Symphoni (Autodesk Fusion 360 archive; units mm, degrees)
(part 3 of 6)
sketch "Sketch8" plane through (0, 0, 18.7) normal (0, 0, 1) x axis (-1, 0, 0)
  line L1 (-53.7625, -51.3779) -> (-53.7625, -105.1735)
  line L2 (53.8484, -51.3779) -> (-53.7625, -51.3779)
  line L3 (53.8484, -76.4735) -> (53.8484, -51.3779)
  line L4 (53.8485, -76.4735) -> (53.8484, -76.4735)
  line L5 (53.8485, -78.1735) -> (53.8485, -76.4735)
  line L6 (53.8484, -78.1735) -> (53.8485, -78.1735)
  line L7 (53.8484, -103.4735) -> (53.8484, -78.1735)
  line L8 (53.8485, -103.4735) -> (53.8484, -103.4735)
  line L9 (53.8485, -105.1735) -> (53.8485, -103.4735)
  line L10 (-53.7625, -105.1735) -> (53.8485, -105.1735)
  line L11 (-53.7625, -15.5942) -> (-53.7625, -42.5942)
  line L12 (53.8484, -15.5942) -> (-53.7625, -15.5942)
  line L13 (53.8484, -42.5942) -> (53.8484, -15.5942)
  line L14 (-53.7625, -42.5942) -> (53.8484, -42.5942)
  line L15 (50.919, -115) -> (-51.081, -115)
  line L16 (60.919, 105) -> (60.919, -105)
  line L17 (-51.081, 115) -> (50.919, 115)
  line L18 (-61.081, -105) -> (-61.081, 105)
  line L19 (39.2266, 75.4964) -> (39.2266, 70.1236)
  line L20 (32.1734, 75.4964) -> (39.2266, 75.4964)
  line L21 (32.1734, 70.1236) -> (32.1734, 75.4964)
  line L22 (39.2266, 70.1236) -> (32.1734, 70.1236)
  line L23 (8.1634, 70.1236) -> (8.1634, 75.4964)
  line L24 (15.2166, 70.1236) -> (8.1634, 70.1236)
  line L25 (15.2166, 75.4964) -> (15.2166, 70.1236)
  line L26 (8.1634, 75.4964) -> (15.2166, 75.4964)
  line L27 (-39.8766, 70.1236) -> (-39.8766, 75.4964)
  line L28 (-32.8234, 70.1236) -> (-39.8766, 70.1236)
  line L29 (-32.8234, 75.4964) -> (-32.8234, 70.1236)
  line L30 (-39.8766, 75.4964) -> (-32.8234, 75.4964)
  line L31 (-8.33, 76.81) -> (-16.33, 76.81)
  line L32 (-16.33, 76.81) -> (-16.33, 68.81)
  line L33 (-8.33, 68.81) -> (-8.33, 76.81)
  line L34 (-16.33, 68.81) -> (-8.33, 68.81)
  line L35 (49.265, 58.435) -> (-47.355, 58.435)
  line L36 (-47.355, 58.435) -> (-47.355, 95.355)
  line L37 (49.265, 95.355) -> (49.265, 58.435)
  line L38 (-47.355, 95.355) -> (49.265, 95.355)
  line L39 (42.697, 79.0319) -> (42.697, 66.5547)
  line L40 (28.703, 66.5547) -> (28.703, 79.0319)
  line L41 (41.9553, 65.813) -> (29.4447, 65.813)
  line L42 (29.372, 79.807) -> (42.028, 79.807)
  line L43 (4.693, 66.5881) -> (4.693, 79.0653)
  line L44 (18.687, 79.0653) -> (18.687, 66.5881)
  line L45 (5.4347, 79.807) -> (17.9453, 79.807)
  line L46 (18.018, 65.813) -> (5.362, 65.813)
  line L47 (-43.347, 66.5881) -> (-43.347, 79.0653)
  line L48 (-29.353, 79.0653) -> (-29.353, 66.5881)
  line L49 (-42.6053, 79.807) -> (-30.0947, 79.807)
  line L50 (-30.022, 65.813) -> (-42.678, 65.813)
  line L51 (25.203, 66.5547) -> (25.203, 79.0319)
  curve K1 (29.4447, 62.313) -> (25.203, 66.5547)
  line L52 (41.9553, 62.313) -> (29.4447, 62.313)
  curve K2 (46.197, 66.5547) -> (41.9553, 62.313)
  line L53 (46.197, 79.0319) -> (46.197, 66.5547)
  curve K3 (42.028, 83.307) -> (46.197, 79.0319)
  line L54 (29.372, 83.307) -> (42.028, 83.307)
  curve K4 (25.203, 79.0319) -> (29.372, 83.307)
  line L55 (22.187, 79.0653) -> (22.187, 66.5881)
  curve K5 (17.9453, 83.307) -> (22.187, 79.0653)
  line L56 (5.4347, 83.307) -> (17.9453, 83.307)
  curve K6 (1.193, 79.0653) -> (5.4347, 83.307)
  line L57 (1.193, 66.5881) -> (1.193, 79.0653)
  curve K7 (5.362, 62.313) -> (1.193, 66.5881)
  line L58 (18.018, 62.313) -> (5.362, 62.313)
  curve K8 (22.187, 66.5881) -> (18.018, 62.313)
  line L59 (-25.853, 79.0653) -> (-25.853, 66.5881)
  curve K9 (-30.0947, 83.307) -> (-25.853, 79.0653)
  line L60 (-42.6053, 83.307) -> (-30.0947, 83.307)
  curve K10 (-46.847, 79.0653) -> (-42.6053, 83.307)
  line L61 (-46.847, 66.5881) -> (-46.847, 79.0653)
  curve K11 (-42.678, 62.313) -> (-46.847, 66.5881)
  line L62 (-30.022, 62.313) -> (-42.678, 62.313)
  curve K12 (-25.853, 66.5881) -> (-30.022, 62.313)
  curve K13 (5.362, 62.313) -> (1.193, 66.5881)
  line L63 (18.018, 62.313) -> (5.362, 62.313)
  curve K14 (22.187, 66.5881) -> (18.018, 62.313)
  line L64 (22.187, 79.0653) -> (22.187, 66.5881)
  curve K15 (17.9453, 83.307) -> (22.187, 79.0653)
  line L65 (5.4347, 83.307) -> (17.9453, 83.307)
  curve K16 (1.193, 79.0653) -> (5.4347, 83.307)
  line L66 (1.193, 66.5881) -> (1.193, 79.0653)
  line L67 (-5.982, 62.313) -> (-18.638, 62.313)
  curve K17 (-1.813, 66.5881) -> (-5.982, 62.313)
  line L68 (-1.813, 79.0653) -> (-1.813, 66.5881)
  curve K18 (-6.0547, 83.307) -> (-1.813, 79.0653)
  line L69 (-18.5653, 83.307) -> (-6.0547, 83.307)
  curve K19 (-22.807, 79.0653) -> (-18.5653, 83.307)
  line L70 (-22.807, 66.5881) -> (-22.807, 79.0653)
  curve K20 (-18.638, 62.313) -> (-22.807, 66.5881)
  line L71 (-35.3, 21.6) -> (-35.3, 21.8)
  line L72 (-35.3, 21.6) -> (-37.3, 21.6)
  line L73 (-37.3, 21.6) -> (-37.3, 21.8)
  line L74 (-37.3, 21.8) -> (-41.05, 21.8)
  line L75 (-31.55, 21.8) -> (-35.3, 21.8)
  line L76 (-41.05, 21.8) -> (-41.05, 22.8)
  line L77 (-31.55, 22.8) -> (-31.55, 21.8)
  line L78 (-41.05, 32.8) -> (-41.05, 22.8)
  line L79 (-31.55, 32.8) -> (-41.05, 32.8)
  line L80 (-31.55, 22.8) -> (-31.55, 32.8)
  line L81 (-11.3, 21.6) -> (-11.3, 21.8)
  line L82 (-11.3, 21.6) -> (-13.3, 21.6)
  line L83 (-13.3, 21.6) -> (-13.3, 21.8)
  line L84 (-13.3, 21.8) -> (-17.05, 21.8)
  line L85 (-7.55, 21.8) -> (-11.3, 21.8)
  line L86 (-17.05, 21.8) -> (-17.05, 22.8)
  line L87 (-7.55, 22.8) -> (-7.55, 21.8)
  line L88 (-17.05, 32.8) -> (-17.05, 22.8)
  line L89 (-7.55, 32.8) -> (-17.05, 32.8)
  line L90 (-7.55, 22.8) -> (-7.55, 32.8)
  line L91 (12.7, 21.6) -> (12.7, 21.8)
  line L92 (12.7, 21.6) -> (10.7, 21.6)
  line L93 (10.7, 21.6) -> (10.7, 21.8)
  line L94 (10.7, 21.8) -> (6.95, 21.8)
  line L95 (16.45, 21.8) -> (12.7, 21.8)
  line L96 (6.95, 21.8) -> (6.95, 22.8)
  line L97 (16.45, 22.8) -> (16.45, 21.8)
  line L98 (6.95, 32.8) -> (6.95, 22.8)
  line L99 (16.45, 32.8) -> (6.95, 32.8)
  line L100 (16.45, 22.8) -> (16.45, 32.8)
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  dimension "d24" = 3.5
  dimension "d25" = 3.5
  dimension "d26" = 3.5
extrude "Extrude7" add sketch "Sketch8" along normal blind 2.349
delete_face "DeleteFace6"
component_insert "Component Insert5"
sketch "Sketch9" plane through (0, 0, 10.185) normal (0, 0, 1) x axis (-1, 0, 0)
  line L1 (-7.83, 77.31) -> (-16.83, 77.31)
  line L2 (-7.83, 68.31) -> (-7.83, 77.31)
  line L3 (-16.83, 68.31) -> (-7.83, 68.31)
  line L4 (-16.83, 77.31) -> (-16.83, 68.31)
  line L5 (27.453, 77.907) -> (28.6, 77.907)
  line L6 (27.453, 78.857) -> (27.453, 77.907)
  line L7 (33.753, 81.057) -> (29.653, 81.057)
  line L8 (33.753, 78.91) -> (33.753, 81.057)
  line L9 (37.647, 78.91) -> (33.753, 78.91)
  line L10 (37.647, 81.057) -> (37.647, 78.91)
  line L11 (41.747, 81.057) -> (37.647, 81.057)
  line L12 (43.947, 77.907) -> (43.947, 78.857)
  line L13 (42.8, 77.907) -> (43.947, 77.907)
  line L14 (42.8, 74.757) -> (42.8, 77.907)
  line L15 (41.8, 74.757) -> (42.8, 74.757)
  line L16 (41.8, 70.863) -> (41.8, 74.757)
  line L17 (42.8, 70.863) -> (41.8, 70.863)
  line L18 (42.8, 67.713) -> (42.8, 70.863)
  line L19 (43.947, 67.713) -> (42.8, 67.713)
  line L20 (43.947, 66.763) -> (43.947, 67.713)
  line L21 (37.647, 64.563) -> (41.747, 64.563)
  line L22 (37.647, 66.71) -> (37.647, 64.563)
  line L23 (33.753, 66.71) -> (37.647, 66.71)
  line L24 (33.753, 64.563) -> (33.753, 66.71)
  line L25 (29.653, 64.563) -> (33.753, 64.563)
  line L26 (27.453, 67.713) -> (27.453, 66.763)
  line L27 (28.6, 67.713) -> (27.453, 67.713)
  line L28 (28.6, 70.863) -> (28.6, 67.713)
  line L29 (29.6, 70.863) -> (28.6, 70.863)
  line L30 (29.6, 74.757) -> (29.6, 70.863)
  line L31 (28.6, 74.757) -> (29.6, 74.757)
  line L32 (28.6, 77.907) -> (28.6, 74.757)
  line L33 (-30.25, 74.757) -> (-29.25, 74.757)
  line L34 (-30.25, 70.863) -> (-30.25, 74.757)
  line L35 (-29.25, 70.863) -> (-30.25, 70.863)
  line L36 (-29.25, 67.713) -> (-29.25, 70.863)
  line L37 (-28.103, 67.713) -> (-29.25, 67.713)
  line L38 (-28.103, 66.763) -> (-28.103, 67.713)
  line L39 (-34.403, 64.563) -> (-30.303, 64.563)
  line L40 (-34.403, 66.71) -> (-34.403, 64.563)
  line L41 (-38.297, 66.71) -> (-34.403, 66.71)
  line L42 (-38.297, 64.563) -> (-38.297, 66.71)
  line L43 (-42.397, 64.563) -> (-38.297, 64.563)
  line L44 (-44.597, 67.713) -> (-44.597, 66.763)
  line L45 (-43.45, 67.713) -> (-44.597, 67.713)
  line L46 (-43.45, 70.863) -> (-43.45, 67.713)
  line L47 (-42.45, 70.863) -> (-43.45, 70.863)
  line L48 (-42.45, 74.757) -> (-42.45, 70.863)
  line L49 (-43.45, 74.757) -> (-42.45, 74.757)
  line L50 (-43.45, 77.907) -> (-43.45, 74.757)
  line L51 (-44.597, 77.907) -> (-43.45, 77.907)
  line L52 (-44.597, 78.857) -> (-44.597, 77.907)
  line L53 (-38.297, 81.057) -> (-42.397, 81.057)
  line L54 (-38.297, 78.91) -> (-38.297, 81.057)
  line L55 (-34.403, 78.91) -> (-38.297, 78.91)
  line L56 (-34.403, 81.057) -> (-34.403, 78.91)
  line L57 (-30.303, 81.057) -> (-34.403, 81.057)
  line L58 (-28.103, 77.907) -> (-28.103, 78.857)
  line L59 (-29.25, 77.907) -> (-28.103, 77.907)
  line L60 (-29.25, 74.757) -> (-29.25, 77.907)
  line L61 (5.59, 70.863) -> (4.59, 70.863)
  line L62 (5.59, 74.757) -> (5.59, 70.863)
  line L63 (4.59, 74.757) -> (5.59, 74.757)
  line L64 (4.59, 77.907) -> (4.59, 74.757)
  line L65 (3.443, 77.907) -> (4.59, 77.907)
  line L66 (3.443, 78.857) -> (3.443, 77.907)
  line L67 (9.743, 81.057) -> (5.643, 81.057)
  line L68 (9.743, 78.91) -> (9.743, 81.057)
  line L69 (13.637, 78.91) -> (9.743, 78.91)
  line L70 (13.637, 81.057) -> (13.637, 78.91)
  line L71 (17.737, 81.057) -> (13.637, 81.057)
  line L72 (19.937, 77.907) -> (19.937, 78.857)
  line L73 (18.79, 77.907) -> (19.937, 77.907)
  line L74 (18.79, 74.757) -> (18.79, 77.907)
  line L75 (17.79, 74.757) -> (18.79, 74.757)
  line L76 (17.79, 70.863) -> (17.79, 74.757)
  line L77 (18.79, 70.863) -> (17.79, 70.863)
  line L78 (18.79, 67.713) -> (18.79, 70.863)
  line L79 (19.937, 67.713) -> (18.79, 67.713)
  line L80 (19.937, 66.763) -> (19.937, 67.713)
  line L81 (13.637, 64.563) -> (17.737, 64.563)
  line L82 (13.637, 66.71) -> (13.637, 64.563)
  line L83 (9.743, 66.71) -> (13.637, 66.71)
  line L84 (9.743, 64.563) -> (9.743, 66.71)
  line L85 (5.643, 64.563) -> (9.743, 64.563)
  line L86 (3.443, 67.713) -> (3.443, 66.763)
  line L87 (4.59, 67.713) -> (3.443, 67.713)
  line L88 (4.59, 70.863) -> (4.59, 67.713)
  line L89 (-47.3233, 95.4822) -> (49.0612, 95.4822)
  line L90 (-47.3233, 58.6231) -> (-47.3233, 95.4822)
  line L91 (49.0612, 58.6231) -> (-47.3233, 58.6231)
  line L92 (49.0612, 95.4822) -> (49.0612, 58.6231)
  arc A1 centre (29.653, 78.857) radius 2.2 clockwise from (27.453, 78.857) to (29.653, 81.057)
  arc A2 centre (41.747, 78.857) radius 2.2 clockwise from (41.747, 81.057) to (43.947, 78.857)
  arc A3 centre (41.747, 66.763) radius 2.2 clockwise from (43.947, 66.763) to (41.747, 64.563)
  arc A4 centre (29.653, 66.763) radius 2.2 clockwise from (29.653, 64.563) to (27.453, 66.763)
  arc A5 centre (-30.303, 66.763) radius 2.2 clockwise from (-28.103, 66.763) to (-30.303, 64.563)
  arc A6 centre (-42.397, 66.763) radius 2.2 clockwise from (-42.397, 64.563) to (-44.597, 66.763)
  arc A7 centre (-42.397, 78.857) radius 2.2 clockwise from (-44.597, 78.857) to (-42.397, 81.057)
  arc A8 centre (-30.303, 78.857) radius 2.2 clockwise from (-30.303, 81.057) to (-28.103, 78.857)
  arc A9 centre (5.643, 78.857) radius 2.2 clockwise from (3.443, 78.857) to (5.643, 81.057)
  arc A10 centre (17.737, 78.857) radius 2.2 clockwise from (17.737, 81.057) to (19.937, 78.857)
  arc A11 centre (17.737, 66.763) radius 2.2 clockwise from (19.937, 66.763) to (17.737, 64.563)
  arc A12 centre (5.643, 66.763) radius 2.2 clockwise from (5.643, 64.563) to (3.443, 66.763)
sketch "Sketch10" plane through (0, 0, 21.049) normal (0, 0, 1) x axis (-1, 0, 0)
  curve K1 (-30.022, 62.313) -> (-25.853, 66.5881)
  line L1 (-42.678, 62.313) -> (-30.022, 62.313)
  curve K2 (-46.847, 66.5881) -> (-42.678, 62.313)
  line L2 (-46.847, 79.0653) -> (-46.847, 66.5881)
  curve K3 (-42.6053, 83.307) -> (-46.847, 79.0653)
  line L3 (-30.0947, 83.307) -> (-42.6053, 83.307)
  curve K4 (-25.853, 79.0653) -> (-30.0947, 83.307)
  line L4 (-25.853, 66.5881) -> (-25.853, 79.0653)
  curve K5 (-22.807, 66.5881) -> (-18.638, 62.313)
  line L5 (-22.807, 79.0653) -> (-22.807, 66.5881)
  curve K6 (-18.5653, 83.307) -> (-22.807, 79.0653)
  line L6 (-6.0547, 83.307) -> (-18.5653, 83.307)
  curve K7 (-1.813, 79.0653) -> (-6.0547, 83.307)
  line L7 (-1.813, 66.5881) -> (-1.813, 79.0653)
  curve K8 (-5.982, 62.313) -> (-1.813, 66.5881)
  line L8 (-18.638, 62.313) -> (-5.982, 62.313)
  line L9 (1.193, 79.0653) -> (1.193, 66.5881)
  curve K9 (1.2034, 79.3649) -> (1.193, 79.0653)
  curve K10 (5.4347, 83.307) -> (1.2034, 79.3649)
  line L10 (17.9453, 83.307) -> (5.4347, 83.307)
  curve K11 (18.2449, 83.2966) -> (17.9453, 83.307)
  curve K12 (22.187, 79.0653) -> (18.2449, 83.2966)
  line L11 (22.187, 66.5881) -> (22.187, 79.0653)
  curve K13 (22.0884, 65.6471) -> (22.187, 66.5881)
  curve K14 (18.018, 62.313) -> (22.0884, 65.6471)
  line L12 (5.362, 62.313) -> (18.018, 62.313)
  curve K15 (2.0685, 63.9442) -> (5.362, 62.313)
  curve K16 (1.3008, 65.6049) -> (2.0685, 63.9442)
  curve K17 (1.193, 66.5881) -> (1.3008, 65.6049)
  curve K18 (29.372, 83.307) -> (25.203, 79.0319)
  line L13 (42.028, 83.307) -> (29.372, 83.307)
  curve K19 (46.197, 79.0319) -> (42.028, 83.307)
  line L14 (46.197, 66.5547) -> (46.197, 79.0319)
  curve K20 (41.9553, 62.313) -> (46.197, 66.5547)
  line L15 (29.4447, 62.313) -> (41.9553, 62.313)
  curve K21 (25.203, 66.5547) -> (29.4447, 62.313)
  line L16 (25.203, 79.0319) -> (25.203, 66.5547)
  line L17 (53.9191, -28.5942) -> (-53.7629, -28.5942)
  line L18 (53.9191, -91.4735) -> (53.9191, -28.5942)
  line L19 (53.8485, -91.4735) -> (53.9191, -91.4735)
  line L20 (53.8485, -93.1735) -> (53.8485, -91.4735)
  line L21 (53.8484, -93.1735) -> (53.8485, -93.1735)
  line L22 (53.8484, -91.4735) -> (53.8484, -93.1735)
  line L23 (-53.7629, -91.4735) -> (53.8484, -91.4735)
  line L24 (-53.7629, -28.5942) -> (-53.7629, -91.4735)
  line L25 (-61.081, -105) -> (-61.081, 105)
  line L26 (50.919, -115) -> (-51.081, -115)
  line L27 (60.919, 105) -> (60.919, -105)
  line L28 (-51.081, 115) -> (50.919, 115)
  line L29 (-53.7629, -28.5942) -> (-53.7629, -91.4735)
  line L30 (-53.7629, -91.4735) -> (53.8484, -91.4735)
  line L31 (53.8484, -91.4735) -> (53.8484, -93.1735)
  line L32 (53.8484, -93.1735) -> (53.8485, -93.1735)
  line L33 (53.8485, -93.1735) -> (53.8485, -91.4735)
  line L34 (53.8485, -91.4735) -> (53.9191, -91.4735)
  line L35 (53.9191, -91.4735) -> (53.9191, -28.5942)
  line L36 (-48.7625, -28.5942) -> (-53.7629, -28.5942)
  line L37 (53.9191, -28.5942) -> (48.9191, -28.5942)
  line L38 (25.203, 79.0319) -> (25.203, 66.5547)
  curve K22 (25.203, 66.5547) -> (29.4447, 62.313)
  line L39 (29.4447, 62.313) -> (41.9553, 62.313)
  curve K23 (41.9553, 62.313) -> (46.197, 66.5547)
  line L40 (46.197, 66.5547) -> (46.197, 79.0319)
  curve K24 (46.197, 79.0319) -> (42.028, 83.307)
  line L41 (42.028, 83.307) -> (29.372, 83.307)
  curve K25 (29.372, 83.307) -> (25.203, 79.0319)
  curve K26 (1.193, 66.5881) -> (1.3008, 65.6049)
  curve K27 (1.3008, 65.6049) -> (2.0685, 63.9442)
  curve K28 (2.0685, 63.9442) -> (5.362, 62.313)
  line L42 (5.362, 62.313) -> (18.018, 62.313)
  curve K29 (18.018, 62.313) -> (22.0884, 65.6471)
  curve K30 (22.0884, 65.6471) -> (22.187, 66.5881)
  line L43 (22.187, 66.5881) -> (22.187, 79.0653)
  curve K31 (22.187, 79.0653) -> (18.2449, 83.2966)
  curve K32 (18.2449, 83.2966) -> (17.9453, 83.307)
  line L44 (17.9453, 83.307) -> (5.4347, 83.307)
  curve K33 (5.4347, 83.307) -> (1.2034, 79.3649)
  curve K34 (1.2034, 79.3649) -> (1.193, 79.0653)
  line L45 (1.193, 79.0653) -> (1.193, 66.5881)
  line L46 (-18.638, 62.313) -> (-5.982, 62.313)
  curve K35 (-5.982, 62.313) -> (-1.813, 66.5881)
  line L47 (-1.813, 66.5881) -> (-1.813, 79.0653)
  curve K36 (-1.813, 79.0653) -> (-6.0547, 83.307)
  line L48 (-6.0547, 83.307) -> (-18.5653, 83.307)
  curve K37 (-18.5653, 83.307) -> (-22.807, 79.0653)
  line L49 (-22.807, 79.0653) -> (-22.807, 66.5881)
  curve K38 (-22.807, 66.5881) -> (-18.638, 62.313)
  line L50 (-25.853, 66.5881) -> (-25.853, 79.0653)
  curve K39 (-25.853, 79.0653) -> (-30.0947, 83.307)
  line L51 (-30.0947, 83.307) -> (-42.6053, 83.307)
  curve K40 (-42.6053, 83.307) -> (-46.847, 79.0653)
  line L52 (-46.847, 79.0653) -> (-46.847, 66.5881)
  curve K41 (-46.847, 66.5881) -> (-42.678, 62.313)
  line L53 (-42.678, 62.313) -> (-30.022, 62.313)
  curve K42 (-30.022, 62.313) -> (-25.853, 66.5881)
  line L54 (-51.081, 115) -> (50.919, 115)
  line L55 (60.919, 105) -> (60.919, -105)
  line L56 (50.919, -115) -> (-51.081, -115)
  line L57 (-61.081, -105) -> (-61.081, 105)
  line L58 (48.9191, -71.4735) -> (48.9191, -28.5942)
  line L59 (-48.7625, -71.4735) -> (48.9191, -71.4735)
  line L60 (-48.7625, -28.5942) -> (-48.7625, -71.4735)
  curve K43 (29.372, 82.807) -> (25.703, 79.0319)
  line L61 (42.028, 82.807) -> (29.372, 82.807)
  curve K44 (45.697, 79.0319) -> (42.028, 82.807)
  line L62 (45.697, 66.5547) -> (45.697, 79.0319)
  curve K45 (41.9553, 62.813) -> (45.697, 66.5547)
  line L63 (29.4447, 62.813) -> (41.9553, 62.813)
  curve K46 (25.703, 66.5547) -> (29.4447, 62.813)
  line L64 (25.703, 79.0319) -> (25.703, 66.5547)
  circle C1 centre (11.7, 27.95) radius 3.4635
  circle C2 centre (-36.3, 27.95) radius 3.25
  circle C3 centre (-12.3, 27.95) radius 3.4635
  circle C4 centre (35.7, 27.95) radius 3.4635
  arc A1 centre (-51.081, -105) radius 10 clockwise from (-51.081, -115) to (-61.081, -105)
  arc A2 centre (50.919, -105) radius 10 clockwise from (60.919, -105) to (50.919, -115)
  arc A3 centre (50.919, 105) radius 10 clockwise from (50.919, 115) to (60.919, 105)
  arc A4 centre (-51.081, 105) radius 10 clockwise from (-61.081, 105) to (-51.081, 115)
  circle C5 centre (35.7, 27.95) radius 3.4635
  circle C6 centre (-12.3, 27.95) radius 3.4635
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  dimension "d29" = 0.5
extrude "Extrude8" new body sketch "Sketch10" profile of K45 K46 K43 L62 K44 L64 L61 L63 against normal blind 7
shell "Shell1" innerThickness 2
copy_paste_bodies "CopyPasteBodies1"
move "Move2"
move "Move3"
sketch "Sketch16" plane through (0, 0, 29.049) normal (0, 0, -1) x axis (1, 0, 0)
  curve K1 (20.297, 66.5547) -> (18.5553, 64.813)
  line L1 (20.297, 79.0319) -> (20.297, 66.5547)
  curve K2 (18.628, 80.807) -> (20.297, 79.0319)
  line L2 (5.972, 80.807) -> (18.628, 80.807)
  curve K3 (4.303, 79.0319) -> (5.972, 80.807)
  line L3 (4.303, 66.5547) -> (4.303, 79.0319)
  curve K4 (6.0447, 64.813) -> (4.303, 66.5547)
  line L4 (18.5553, 64.813) -> (6.0447, 64.813)
  line L5 (13.2555, 73.9121) -> (11.2555, 73.9121)
  line L6 (13.2555, 71.9121) -> (13.2555, 73.9121)
  line L7 (11.2555, 71.9121) -> (13.2555, 71.9121)
  line L8 (11.2555, 73.9121) -> (11.2555, 71.9121)
  line L9 (14.2555, 74.9121) -> (10.2555, 74.9121)
  line L10 (14.2555, 70.9121) -> (14.2555, 74.9121)
  line L11 (10.2555, 70.9121) -> (14.2555, 70.9121)
  line L12 (10.2555, 74.9121) -> (10.2555, 70.9121)
  line L13 (11.2555, 73.9121) -> (13.2555, 73.9121)
  line L14 (11.2555, 71.9121) -> (11.2555, 73.9121)
  line L15 (13.2555, 71.9121) -> (11.2555, 71.9121)
  line L16 (13.2555, 73.9121) -> (13.2555, 71.9121)
extrude "Extrude12" add sketch "Sketch16" profile of L5 L6 L7 L8 L9 L10 L11 L12 L13 L14 L15 L16 along normal blind 4
sketch "Sketch17" plane through (0, 0, 25.049) normal (0, 0, -1) x axis (1, 0, 0)
  line L1 (13.2555, 71.9121) -> (13.2555, 73.9121)
  line L2 (11.2555, 71.9121) -> (13.2555, 71.9121)
  line L3 (11.2555, 73.9121) -> (11.2555, 71.9121)
  line L4 (13.2555, 73.9121) -> (11.2555, 73.9121)
  line L5 (14.2555, 70.9121) -> (10.2555, 70.9121)
  line L6 (14.2555, 74.9121) -> (14.2555, 70.9121)
  line L7 (10.2555, 74.9121) -> (14.2555, 74.9121)
  line L8 (10.2555, 70.9121) -> (10.2555, 74.9121)
  line L9 (11.2305, 71.4167) -> (13.2805, 71.4167)
  line L10 (11.2305, 74.4667) -> (11.2305, 71.4167)
  line L11 (13.2805, 74.4667) -> (11.2305, 74.4667)
  line L12 (13.2805, 71.4167) -> (13.2805, 74.4667)
  line L13 (11.2305, 74.4667) -> (13.2805, 71.4167)
  line L14 (13.2805, 74.4667) -> (11.2305, 71.4167)
  point P14 (12.2555, 72.9417)
  point P12 (11.2305, 74.4667)
  point P13 (13.2805, 74.4667)
  point P11 (11.2305, 71.4167)
  horizontal L9
  perpendicular L9 L10
  parallel L9 L11
  parallel L10 L12
  coincident L13 P14
  coincident L14 P14
  dimension "d52" distance P12 P13 = 2.05
  dimension "d53" distance P11 P12 = 3.05
extrude "Extrude13" cut sketch "Sketch17" profile of L1 L2 L3 L4 L9 L10 L11 L12 against normal blind 3
offset_faces "OffsetFaces3" distance 0.5
offset_faces "OffsetFaces4" distance -0.2
base_feature "Base Feature1"
sketch "Sketch11" plane through (0, 0, 50.1422) normal (0, 0, -1) x axis (1, 0, 0)
  line L1 (0.75, -27.6079) -> (0.75, -26.0255)
  line L2 (2.3324, -27.6079) -> (0.75, -27.6079)
  line L3 (0.75, -29.1079) -> (2.3324, -29.1079)
  line L4 (0.75, -30.6902) -> (0.75, -29.1079)
  line L5 (-0.75, -29.1079) -> (-0.75, -30.6902)
  line L6 (-2.3324, -29.1079) -> (-0.75, -29.1079)
  line L7 (-0.75, -27.6079) -> (-2.3324, -27.6079)
  line L8 (-0.75, -26.0255) -> (-0.75, -27.6079)
  circle C1 centre (0, -28.3579) radius 2.7
  arc A1 centre (0, -28.3579) radius 2.45 clockwise from (2.3324, -27.6079) to (2.3324, -29.1079)
  arc A2 centre (0, -28.3579) radius 2.45 clockwise from (0.75, -30.6902) to (-0.75, -30.6902)
  arc A3 centre (0, -28.3579) radius 2.45 clockwise from (-2.3324, -29.1079) to (-2.3324, -27.6079)
  arc A4 centre (0, -28.3579) radius 2.45 clockwise from (-0.75, -26.0255) to (0.75, -26.0255)
sketch "Sketch12" plane through (0, 0, 50.1422) normal (0, 0, -1) x axis (1, 0, 0)
  circle C1 centre (0, -28.3579) radius 2.9
  circle C2 centre (0, -28.3579) radius 2.7
  circle C3 centre (0, -28.3579) radius 14.7088
  concentric C1 C3
extrude "Extrude1" cut sketch "Sketch12" profile of C1 C3 against normal blind 10 and along normal blind 2
extrude "Extrude2" cut sketch "Sketch12" profile of C1 C2 blind -4 from offset -5
position "Position6"
combine "Combine2"
position "Position7"
sketch "Sketch13" plane through (0, 0, 4.51) normal (0, 0, -1) x axis (1, 0, 0)
  line L1 (45.3505, 93.0621) -> (45.3505, 60.1421)
  line L2 (43.3505, 95.0621) -> (45.3505, 93.0621)
  line L3 (-45.6595, 95.0621) -> (43.3505, 95.0621)
  line L4 (-47.6595, 93.0621) -> (-45.6595, 95.0621)
  line L5 (-47.6595, 60.1421) -> (-47.6595, 93.0621)
  line L6 (-45.6595, 58.1421) -> (-47.6595, 60.1421)
  line L7 (43.3505, 58.1421) -> (-45.6595, 58.1421)
  line L8 (45.3505, 60.1421) -> (43.3505, 58.1421)
  line L9 (19.0111, 53.6021) -> (-14.1013, 53.6021)
  line L10 (19.0111, 98.6021) -> (19.0111, 53.6021)
  line L11 (-14.1013, 98.6021) -> (19.0111, 98.6021)
  line L12 (-14.1013, 53.6021) -> (-14.1013, 98.6021)
  line L13 (0, 0) -> (0, 115)
  line L14 (45.3505, 76.6021) -> (-47.6595, 76.6021)
  line L15 (19.0111, 95.6021) -> (-14.1013, 95.6021)
  line L16 (19.0111, 57.6021) -> (-14.1013, 57.6021)
  line L17 (7.4583, 68.3957) -> (16.6508, 68.3957)
  line L18 (7.4583, 78.6095) -> (7.4583, 68.3957)
  line L19 (16.6508, 78.6095) -> (7.4583, 78.6095)
  line L20 (16.6508, 68.3957) -> (16.6508, 78.6095)
  line L21 (-14.1013, 69.7867) -> (-7.9545, 69.7867)
  line L22 (-14.1013, 76.1021) -> (-14.1013, 69.7867)
  line L23 (-7.9545, 76.1021) -> (-14.1013, 76.1021)
  line L24 (-7.9545, 69.7867) -> (-7.9545, 76.1021)
  circle C1 centre (-44.9545, 62.2071) radius 1.55
  circle C2 centre (-39.5845, 67.8321) radius 0.5
  circle C3 centre (-31.9645, 67.8321) radius 0.5
  circle C4 centre (-35.7745, 72.9121) radius 1.9939
  circle C5 centre (-30.7745, 72.9121) radius 0.85
  circle C6 centre (-15.5745, 67.8321) radius 0.5
  circle C7 centre (-7.9545, 67.8321) radius 0.5
  circle C8 centre (-11.7645, 72.9121) radius 1.9939
  circle C9 centre (39.2555, 62.2071) radius 1.55
  circle C10 centre (9.7155, 69.9121) radius 0.425
  circle C11 centre (12.2555, 69.9121) radius 0.425
  circle C12 centre (14.7955, 69.9121) radius 0.425
  circle C13 centre (32.4655, 67.8321) radius 0.425
  circle C14 centre (40.0855, 67.8321) radius 0.425
  circle C15 centre (31.2755, 72.9121) radius 0.85
  circle C16 centre (36.2755, 72.9121) radius 1.9939
  circle C17 centre (41.2755, 72.9121) radius 0.85
  circle C18 centre (-40.7745, 72.9121) radius 0.85
  circle C19 centre (-31.9645, 75.4521) radius 0.75
  circle C20 centre (-38.2845, 77.9921) radius 0.8
  circle C21 centre (-16.7645, 72.9121) radius 0.85
  circle C22 centre (-6.7645, 72.9121) radius 0.85
  circle C23 centre (-7.9545, 75.4521) radius 0.75
  circle C24 centre (-14.2745, 77.9921) radius 0.75
  circle C25 centre (-44.6645, 83.6171) radius 1.55
  circle C26 centre (9.7155, 75.9121) radius 0.425
  circle C27 centre (12.2555, 75.9121) radius 0.425
  circle C28 centre (14.7955, 75.9121) radius 0.425
  circle C29 centre (40.0855, 75.4521) radius 0.75
  circle C30 centre (33.7655, 77.9921) radius 0.75
  circle C31 centre (39.2555, 83.6171) radius 1.55
  point P1 (0, 0)
  point P46 (0, 0)
  point P47 (-47.6595, 76.6021)
  point P48 (45.3505, 76.6021)
  point P49 (-14.1013, 95.6021)
  point P50 (19.0111, 95.6021)
  point P51 (-14.1013, 57.6021)
  point P52 (19.0111, 57.6021)
  point P59 (-14.1013, 76.1021)
  horizontal L9
  vertical L10
  horizontal L11
  vertical L12
  coincident P1 P46
  vertical L13
  midpoint L5 P47
  midpoint L1 P48
  coincident L12 P49
  coincident L10 P50
  perpendicular L10 L15
  symmetric L14 P49 P51
  symmetric L14 P50 P52
  horizontal L17
  vertical L18
  horizontal L19
  vertical L20
  horizontal L21
  vertical L22
  horizontal L23
  vertical L24
  midpoint L12 P59
  dimension "d40" distance L11 L14 = 22
  dimension "d41" distance L9 L14 = 23
  dimension "d42" distance L11 L15 = 3
extrude "Extrude9" new body sketch "Sketch13" profile of L3 L7 C7 C10 C11 C12 C22 C23 C24 C26 C27 C28 L9 L10 L11 L12 L15 L16 L17 L18 L19 L20 L21 L23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 along normal blind 2.005
extrude "Extrude10" new body sketch "Sketch13" profile of L9 L10 L11 L12 L15 L16 to an object
combine "Combine3"
sketch "Sketch14" plane through (19.0111, 0, 0) normal (1, 0, 0) x axis (0, 1, 0)
  line L1 (-98.6021, 18.7) -> (-95.6021, 18.7)
  line L2 (-98.6021, 2.505) -> (-98.6021, 18.7)
  line L3 (-95.6021, 18.7) -> (-95.6021, 4.51)
  line L4 (-95.6021, 4.51) -> (-57.6021, 4.51)
  line L5 (-53.6021, 2.505) -> (-98.6021, 2.505)
  line L6 (-53.6021, 18.7) -> (-53.6021, 2.505)
  line L7 (-57.6021, 18.7) -> (-53.6021, 18.7)
  line L8 (-57.6021, 4.51) -> (-57.6021, 18.7)
sketch "Sketch15" plane through (0, 0, 18.7) normal (0, 0, 1) x axis (-1, 0, 0)
  line L1 (-19.0111, 95.6021) -> (-19.0111, 98.6021)
  line L2 (14.1013, 95.6021) -> (-19.0111, 95.6021)
  line L3 (14.1013, 98.6021) -> (14.1013, 95.6021)
  line L4 (-19.0111, 98.6021) -> (14.1013, 98.6021)
  line L5 (14.1018, 95.6021) -> (-19.0111, 95.6021)
  line L6 (14.1018, 109.6107) -> (14.1018, 95.6021)
  line L7 (-19.0111, 109.6107) -> (14.1018, 109.6107)
  line L8 (-19.0111, 95.6021) -> (-19.0111, 109.6107)
  line L9 (-47.3233, 95.4822) -> (-47.3233, 58.6231)
  line L10 (65, 77.0527) -> (-47.3233, 77.0527)
  line L11 (14.1018, 58.5032) -> (-19.0111, 58.5032)
  line L12 (14.1018, 44.4946) -> (14.1018, 58.5032)
  line L13 (-19.0111, 44.4946) -> (14.1018, 44.4946)
  line L14 (-19.0111, 58.5032) -> (-19.0111, 44.4946)
  point P3 (-19.0111, 95.6021)
  point P6 (-19.0111, 95.6021)
  point P12 (-47.3233, 77.0527)
  point P14 (-19.0111, 58.5032)
  point P7 (14.1018, 95.6021)
  point P15 (14.1018, 58.5032)
  point P8 (14.1018, 109.6107)
  point P16 (14.1018, 44.4946)
  point P9 (-19.0111, 109.6107)
  point P17 (-19.0111, 44.4946)
  horizontal L5
  vertical L6
  horizontal L7
  vertical L8
  coincident P3 P6
  midpoint L9 P12
  perpendicular L9 L10
  symmetric P6 L10 P14
  symmetric P7 L10 P15
  symmetric P8 L10 P16
  symmetric P9 L10 P17
extrude "Extrude11" add sketch "Sketch15" profile of L4 L6 L7 L8 L11 L12 L13 L14 against normal blind 1.5
offset_faces "OffsetFaces5" distance 0.3
offset_faces "OffsetFaces6" distance 0.3
offset_faces "OffsetFaces7" distance 1.5
move "Move4"
move "Move5"
sketch "Sketch18" plane through (0, 0, 16.7) normal (0, 0, -1) x axis (1, 0, 0)
  line L1 (-48.9191, -18.5942) -> (48.7625, -18.5942)
  line L2 (-48.9191, -71.4735) -> (-48.9191, -18.5942)
  line L3 (48.7625, -71.4735) -> (-48.9191, -71.4735)
  line L4 (48.7625, -18.5942) -> (48.7625, -71.4735)
extrude "Extrude14" cut sketch "Sketch18" against normal blind 2
move "Move6"
move "Move7"
copy_paste_bodies "CopyPasteBodies2"
move "Move8"
copy_paste_bodies "CopyPasteBodies3"
move "Move9"
component_insert "Component Insert7"
chamfer "Chamfer1" distance 7
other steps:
base_feature "Base Feature1"
base_feature "Base Feature1"
base_feature "Base Feature2"
base_feature "Base Feature3"
create_component "CreateComponent1"
remove_body "RemoveBody1"
create_component "CreateComponent2"
remove_body "RemoveBody1"

design "Symphoni_BL_Speaker_Copy" references "PCM5102_Modul_ksu_detail"
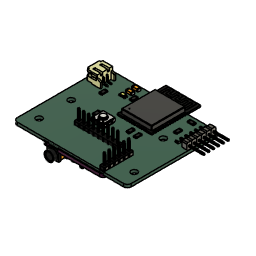
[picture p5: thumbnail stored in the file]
description: KiCad electronic assembly
part number: Symphoni_BL_Speaker_Copy 1
description: Part Number
part number: Symphoni_BL_Speaker_Copy 1.1.1
part number: Symphoni_BL_Speaker_Copy 1.1.2
part number: PinHeader-01x06_P2.54mm_Vertical_THT
part number: Symphoni_BL_Speaker_Copy 1.2.1
part number: Symphoni_BL_Speaker_Copy 1.2.2
part number: Header_SMD_01x06_P2.54mm_Horizontal_Male
part number: Ceramic
part number: Contacts
part number: Contacts (Mirror #1)
base_feature "Base Feature1"
base_feature "Base Feature1"
base_feature "Base Feature1"
base_feature "Base Feature1"
base_feature "Base Feature1"
base_feature "Base Feature1"
base_feature "Base Feature1"
base_feature "Base Feature1"
base_feature "Base Feature1"
base_feature "Base Feature1"
base_feature "Base Feature1"
base_feature "Base Feature1"
base_feature "Base Feature1"
base_feature "Base Feature1"
base_feature "Base Feature1"
base_feature "Base Feature1"
base_feature "Base Feature1"
base_feature "Base Feature1"
base_feature "Base Feature1"
base_feature "Base Feature1"
base_feature "Base Feature1"
base_feature "Base Feature1"
base_feature "Base Feature1"
base_feature "Base Feature1"
base_feature "Base Feature1"
base_feature "Base Feature1"
base_feature "Base Feature1"
base_feature "Base Feature1"
component_insert "Component Insert"
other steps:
create_component "CreateComponent1"
create_component "CreateComponent1"
create_component "CreateComponent2"
create_component "CreateComponent2"
create_component "CreateComponent1"
create_component "CreateComponent2"
create_component "CreateComponent3"
create_component "CreateComponent1"
create_component "CreateComponent2"
create_component "CreateComponent3"
create_component "CreateComponent4"
create_component "CreateComponent4"
create_component "CreateComponent1"
create_component "CreateComponent2"
create_component "CreateComponent3"
create_component "CreateComponent4"
create_component "CreateComponent5"
create_component "CreateComponent1"
create_component "CreateComponent2"
create_component "CreateComponent3"
create_component "CreateComponent6"
create_component "CreateComponent1"
create_component "CreateComponent2"
create_component "CreateComponent3"
create_component "CreateComponent7"
create_component "CreateComponent1"
create_component "CreateComponent2"
create_component "CreateComponent1"
create_component "CreateComponent2"
create_component "CreateComponent3"
create_component "CreateComponent4"
create_component "CreateComponent3"
create_component "CreateComponent4"
create_component "CreateComponent8"
create_component "CreateComponent9"
create_component "CreateComponent10"

design "XH-M577"
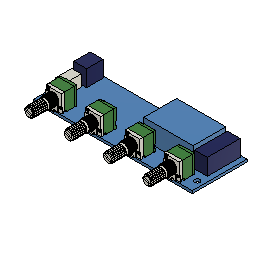
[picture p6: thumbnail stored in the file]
description: Part Number
part number: XH-M577
part number: pcb
part number: Poti Cuadrado mini
part number: RV097NS_CORTO
part number: RV097NS_CORTO_1
part number: RV097NS_CORTO_2
part number: RV097NS_CORTO_3
part number: terminals
base_feature "Base Feature1"
base_feature "Base Feature1"
base_feature "Base Feature1"
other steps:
create_component "CreateComponent1"
create_component "CreateComponent2"
create_component "CreateComponent1"
create_component "CreateComponent3"
create_component "CreateComponent4"
create_component "CreateComponent5"
create_component "CreateComponent6"

design "Symphoni"
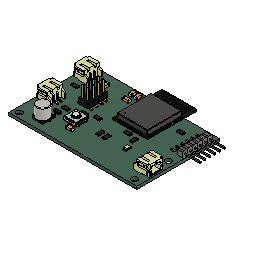
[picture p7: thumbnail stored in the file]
description: KiCad electronic assembly
part number: Symphoni 1
description: Part Number
part number: Ceramic
part number: Contacts
part number: Contacts (Mirror #1)
part number: Overcoat
part number: Resistor-1206
part number: Body
part number: Contact
part number: ContactClone
part number: Capacitor-1206
base_feature "Base Feature1"
base_feature "Base Feature1"
base_feature "Base Feature1"
base_feature "Base Feature1"
base_feature "Base Feature1"
base_feature "Base Feature1"
base_feature "Base Feature1"
base_feature "Base Feature1"
base_feature "Base Feature1"
base_feature "Base Feature1"
base_feature "Base Feature1"
base_feature "Base Feature1"
base_feature "Base Feature1"
base_feature "Base Feature1"
base_feature "Base Feature1"
base_feature "Base Feature1"
base_feature "Base Feature1"
base_feature "Base Feature1"
base_feature "Base Feature1"
base_feature "Base Feature1"
base_feature "Base Feature1"
base_feature "Base Feature1"
base_feature "Base Feature1"
base_feature "Base Feature1"
base_feature "Base Feature1"
base_feature "Base Feature1"
base_feature "Base Feature1"
base_feature "Base Feature1"
base_feature "Base Feature1"
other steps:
create_component "CreateComponent1"
create_component "CreateComponent1"
create_component "CreateComponent2"
create_component "CreateComponent3"
create_component "CreateComponent4"
create_component "CreateComponent2"
create_component "CreateComponent1"
create_component "CreateComponent2"
create_component "CreateComponent3"
create_component "CreateComponent3"
create_component "CreateComponent1"
create_component "CreateComponent2"
create_component "CreateComponent4"
create_component "CreateComponent5"
create_component "CreateComponent1"
create_component "CreateComponent2"
create_component "CreateComponent3"
create_component "CreateComponent4"
create_component "CreateComponent6"
create_component "CreateComponent7"
create_component "CreateComponent8"
create_component "CreateComponent1"
create_component "CreateComponent2"
create_component "CreateComponent3"
create_component "CreateComponent4"
create_component "CreateComponent9"
create_component "CreateComponent1"
create_component "CreateComponent2"
create_component "CreateComponent1"
create_component "CreateComponent2"
create_component "CreateComponent3"
create_component "CreateComponent4"
create_component "CreateComponent3"
create_component "CreateComponent4"
create_component "CreateComponent10"
create_component "CreateComponent11"

design "Cherry MX Keycap"
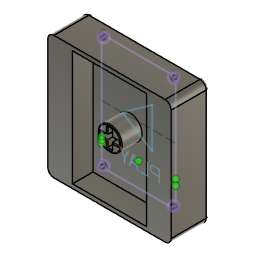
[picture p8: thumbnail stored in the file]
part number: Cherry MX Keycap
base_feature "Base Feature"
split "Split1"
work_plane "WorkPlane1" AlongDistance -6
split "Split2"
sketch "Sketch1" plane through (0, 5.5, 0) normal (0, -1, 0) x axis (-1, 0, 0)
  line L1 (10, 15) -> (-10, 15)
  line L2 (10, -15) -> (10, 15)
  line L3 (-10, -15) -> (10, -15)
  line L4 (-10, 15) -> (-10, -15)
  line L5 (10, -15) -> (-10, 15)
  line L6 (-10, -15) -> (10, 15)
  point P6 (0, 0)
  point P1 (0, 0)
  point P4 (10, -15)
  point P5 (-10, -15)
  horizontal L1
  perpendicular L1 L2
  parallel L1 L3
  parallel L2 L4
  coincident L5 P6
  coincident L6 P6
  coincident P1 P6
  dimension "d13" distance L1 L3 = 30
  dimension "d14" distance P4 P5 = 20
extrude "Extrude1" new body sketch "Sketch1" profile of L1 L2 L3 L4 along normal blind 9
shell "Shell1" innerThickness 1
fillet "Fillet1" radius 1.5
fillet "Fillet2" radius 0.5
sketch "Sketch2" plane through (0, 5.5, 0) normal (0, 1, 0) x axis (-1, 0, 0)
  line L1 (-8.5, 14.5) -> (8.5, 14.5)
  line L2 (-9.5, -13.5) -> (-9.5, 13.5)
  line L3 (8.5, -14.5) -> (-8.5, -14.5)
  line L4 (9.5, 13.5) -> (9.5, -13.5)
  line L5 (-9, -13.5) -> (-9, 13.5)
  line L6 (8.5, -14) -> (-8.5, -14)
  line L7 (9, 13.5) -> (9, -13.5)
  line L8 (-8.5, 14) -> (8.5, 14)
  arc A1 centre (8.5, 13.5) radius 1 clockwise from (8.5, 14.5) to (9.5, 13.5)
  arc A2 centre (-8.5, 13.5) radius 1 clockwise from (-9.5, 13.5) to (-8.5, 14.5)
  arc A3 centre (-8.5, -13.5) radius 1 clockwise from (-8.5, -14.5) to (-9.5, -13.5)
  arc A4 centre (8.5, -13.5) radius 1 clockwise from (9.5, -13.5) to (8.5, -14.5)
  arc A5 centre (-8.5, -13.5) radius 0.5 clockwise from (-8.5, -14) to (-9, -13.5)
  arc A6 centre (8.5, -13.5) radius 0.5 clockwise from (9, -13.5) to (8.5, -14)
  arc A7 centre (8.5, 13.5) radius 0.5 clockwise from (8.5, 14) to (9, 13.5)
  arc A8 centre (-8.5, 13.5) radius 0.5 clockwise from (-9, 13.5) to (-8.5, 14)
  dimension "d19" = -0.5
sketch "Sketch4" plane through (0, 4.5, 0) normal (0, -1, 0) x axis (1, 0, 0)
  line L1 (-9, 14) -> (9, 14)
  line L2 (-9, -14) -> (-9, 14)
  line L3 (9, -14) -> (-9, -14)
  line L4 (9, 14) -> (9, -14)
  line L5 (8.5, 14.5) -> (-8.5, 14.5)
  line L6 (9.5, -13.5) -> (9.5, 13.5)
  line L7 (-8.5, -14.5) -> (8.5, -14.5)
  line L8 (-9.5, 13.5) -> (-9.5, -13.5)
  arc A1 centre (-8.5, 13.5) radius 1 clockwise from (-9.5, 13.5) to (-8.5, 14.5)
  arc A2 centre (8.5, 13.5) radius 1 clockwise from (8.5, 14.5) to (9.5, 13.5)
  arc A3 centre (8.5, -13.5) radius 1 clockwise from (9.5, -13.5) to (8.5, -14.5)
  arc A4 centre (-8.5, -13.5) radius 1 clockwise from (-8.5, -14.5) to (-9.5, -13.5)
extrude "Extrude4" add sketch "Sketch4" profile of L1 L2 L3 L4 along normal blind 3
extrude "Extrude2" cut sketch "Sketch2" profile of A8 L5 A5 A6 L7 L6 A7 L8 against normal blind 1.9
split "Split3"
move "Move1"
sketch "Sketch5" plane through (0, 3.6, 0) normal (0, 1, 0) x axis (-1, 0, 0)
  line L1 (-9, -13.5) -> (-9, 13.5)
  line L2 (8.5, -14) -> (-8.5, -14)
  line L3 (9, 13.5) -> (9, -13.5)
  line L4 (-8.5, 14) -> (8.5, 14)
  circle C1 centre (0, 0) radius 2.9
  arc A1 centre (-8.5, 13.5) radius 0.5 clockwise from (-9, 13.5) to (-8.5, 14)
  arc A2 centre (-8.5, -13.5) radius 0.5 clockwise from (-8.5, -14) to (-9, -13.5)
  arc A3 centre (8.5, -13.5) radius 0.5 clockwise from (9, -13.5) to (8.5, -14)
  arc A4 centre (8.5, 13.5) radius 0.5 clockwise from (8.5, 14) to (9, 13.5)
extrude "Extrude5" add sketch "Sketch5" profile of C1 against normal blind 3
sketch "Sketch6" plane through (0, 3.6, 0) normal (0, 1, 0) x axis (-1, 0, 0)
  line L1 (-9, -13.5) -> (-9, 13.5)
  line L2 (8.5, -14) -> (-8.5, -14)
  line L3 (9, 13.5) -> (9, -13.5)
  line L4 (-8.5, 14) -> (8.5, 14)
  line L5 (-3.2643, -4.5265) -> (-3.2643, 5.1888)
  line L6 (4, 0) -> (-3.2643, -4.5265)
  line L7 (-3.2643, 5.1888) -> (4, 0)
  line L8 (-9, 0) -> (9, 0)
  curve K1
  curve K2
  curve K3
  curve K4
  arc A1 centre (-8.5, 13.5) radius 0.5 clockwise from (-9, 13.5) to (-8.5, 14)
  arc A2 centre (-8.5, -13.5) radius 0.5 clockwise from (-8.5, -14) to (-9, -13.5)
  arc A3 centre (8.5, -13.5) radius 0.5 clockwise from (9, -13.5) to (8.5, -14)
  arc A4 centre (8.5, 13.5) radius 0.5 clockwise from (8.5, 14) to (9, 13.5)
  point P17 (9, 0)
  point P18 (-9, 0)
  parallel L1 L5
  midpoint L3 P17
  midpoint L1 P18
  coincident L1
  coincident L3
  dimension "d20" Text1-Height = 3
offset_faces "OffsetFaces1" distance 5
offset_faces "OffsetFaces2" distance -5

design "RFID-RC522 simple"
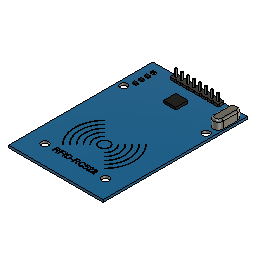
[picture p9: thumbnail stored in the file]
part number: RFID-RC522 simple
base_feature "Base Feature"

design "Playback_Controls_larger"
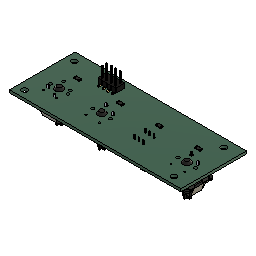
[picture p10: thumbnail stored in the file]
description: KiCad electronic assembly
part number: Playback_Controls 1
description: Part Number
part number: Ceramic
part number: Contacts
part number: Contacts (Mirror #1)
part number: Overcoat
part number: Resistor-1206
part number: PinHeader_2x04_P2.54mm_Vertical_SMD
part number: MX1A-11NN
part number: SW_Btn_XLX
part number: Playback_Controls_PCB
base_feature "Base Feature1"
base_feature "Base Feature1"
base_feature "Base Feature1"
base_feature "Base Feature1"
base_feature "Base Feature1"
base_feature "Base Feature1"
base_feature "Base Feature1"
base_feature "Base Feature1"
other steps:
create_component "CreateComponent1"
create_component "CreateComponent1"
create_component "CreateComponent2"
create_component "CreateComponent3"
create_component "CreateComponent4"
create_component "CreateComponent2"
create_component "CreateComponent3"
create_component "CreateComponent4"
create_component "CreateComponent5"

design "Bearing_Test" references "RFID-RC522 simple", "N20 DC MOTOR"
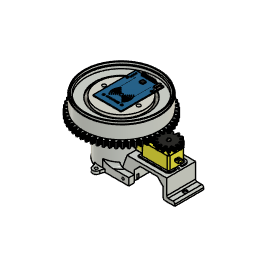
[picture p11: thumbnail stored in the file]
part number: MotorDCTT
parameter "d95" = 10
sketch "Sketch1" plane through (0, 0, 0) normal (0, 0, 1) x axis (1, 0, 0)
  circle C1 centre (0, 0) radius 39
  circle C2 centre (0, 0) radius 30
  circle C3 centre (0, 0) radius 32.9
  circle C4 centre (0, 0) radius 37
  point P1 (0, 0)
  point P2 (0, 0)
  coincident P1 P2
  concentric C1 C2
  dimension "d1" diameter C1 = 78
  dimension "d2" diameter C2 = 60
  dimension "d3" = 2.9
  dimension "d4" = -2
extrude "Extrude1" new body sketch "Sketch1" profile of C2 C3 distance 10
extrude "Extrude2" add sketch "Sketch1" profile of C3 C4 distance 9.8
extrude "Extrude3" new body sketch "Sketch1" profile of C1 C4 distance 10
component_insert "Component Insert1"
sketch "Sketch1" plane through (0, 0, 5) normal (0, 0, 1) x axis (-1, 0, 0)
  circle C1 centre (0, 0) radius 30
  circle C2 centre (0, 0) radius 32.9
extrude "Extrude1" new body sketch "Sketch1" along normal blind 10
extrude "Extrude2" add sketch "Sketch1" profile of C1 against normal blind 70
position "Position1"
position "Position2"
sketch "Sketch2" plane through (0, 0, 0) normal (0, 1, 0) x axis (1, 0, 0)
  line L1 (-11, -16) -> (11, -16)
  line L2 (-11, -5) -> (-11, -16)
  line L3 (11, -5) -> (-11, -5)
  line L4 (11, -16) -> (11, -5)
  horizontal L1
  vertical L2
  horizontal L3
  vertical L4
shell "Shell1" innerThickness 13
extrude "Extrude3" cut sketch "Sketch2" along normal blind 39
sketch "Sketch2" plane through (0, 0, 2) normal (0, 0, -1) x axis (1, 0, 0)
  circle C1 centre (0, 0) radius 17
  circle C2 centre (0, 0) radius 17
  circle C3 centre (0, 0) radius 12.4353
  dimension "d34" = -4.5647
extrude "Extrude4" cut sketch "Sketch2" profile of C3 against normal blind 15
position "Position3"
sketch "Sketch1" plane through (0, 0, 5) normal (0, 0, 1) x axis (-1, 0, 0)
  circle C1 centre (0, 0) radius 37
  circle C2 centre (0, 0) radius 39
  circle C3 centre (0, 0) radius 53.6774
  circle C4 centre (0, 0) radius 48.4417
  circle C5 centre (0, 0) radius 75
  point P1 (0, 0)
  point P4 (0, 0)
  concentric C1 C3
  coincident P1 P4
  concentric C1 C5
  dimension "d72" diameter C5 = 150
extrude "Extrude1" new body sketch "Sketch1" profile of C1 C2 along normal blind 4
extrude "Extrude2" add sketch "Sketch1" profile of C2 C3 C4 along normal blind 4 and against normal blind 10
extrude "Extrude3" add sketch "Sketch1" profile of C3 C4 C5 along normal blind 18
component_from_bodies "Body->Comp1"
component_from_bodies "Body->Comp2"
sketch "Sketch3" plane through (0, 0, 15) normal (0, 0, 1) x axis (-1, 0, 0)
  line L1 (11, -31.0066) -> (11, -5.7996)
  line L2 (-11, -5.7996) -> (-11, -31.0066)
  arc A1 centre (0, 0) radius 12.4353 clockwise from (-11, -5.7996) to (11, -5.7996)
  arc A2 centre (0, 0) radius 32.9 clockwise from (-11, -31.0066) to (11, -31.0066)
  circle C1 centre (-12.6446, 12.0612) radius 1.5
  circle C2 centre (12.3554, 12.0612) radius 1.5
  circle C3 centre (16.8554, -24.9388) radius 1.5
  circle C4 centre (-17.1446, -24.9388) radius 1.5
  circle C5 centre (0, 0) radius 24
  circle C6 centre (-24, 0) radius 2.5
  circle C7 centre (24, 0) radius 2.5
  point P12 (-24, 0)
  point P13 (24, 0)
  coincident C5 P12
  coincident C5 P13
  concentric A2 C5
  dimension "d56" diameter C6 = 5
  dimension "d57" diameter C7 = 5
extrude "Extrude5" cut sketch "Sketch3" profile of C1 C2 C3 C4 against normal blind 10
sketch "Sketch3" plane through (0, 0, 15) normal (0, 0, 1) x axis (-1, 0, 0)
  line L1 (11, -31.0066) -> (11, -5.7996)
  line L2 (-11, -5.7996) -> (-11, -31.0066)
  line L3 (11, -24.0899) -> (-11, -24.0899)
  line L4 (11, -31.0066) -> (11, -24.0899)
  line L5 (-11, -31.0066) -> (11, -31.0066)
  line L6 (-11, -24.0899) -> (-11, -31.0066)
  circle C1 centre (12.3554, 12.0612) radius 1.5
  circle C2 centre (16.8554, -24.9388) radius 1.5
  circle C3 centre (-12.6446, 12.0612) radius 1.5
  circle C4 centre (-17.1446, -24.9388) radius 1.5
  arc A1 centre (0, 0) radius 12.4353 clockwise from (-11, -5.7996) to (11, -5.7996)
  arc A2 centre (0, 0) radius 32.9 clockwise from (-11, -31.0066) to (11, -31.0066)
  circle C5 centre (0, 0) radius 32.9
  point P9 (11, -31.0066)
  point P13 (11, -31.0066)
  point P11 (-11, -24.0899)
  horizontal L3
  vertical L4
  horizontal L5
  vertical L6
  coincident P9 P13
  coincident L2 P11
  dimension "d96" TaperAngle = 0
extrude "Extrude5" cut sketch "Sketch3" profile of A1 L1 L2 L3 L4 L5 L6 C5 blind -20 from offset -50
sketch "Sketch4" plane through (0, 0, 23) normal (0, 0, 1) x axis (-1, 0, 0)
  circle C1 centre (0, 0) radius 48.4417
  circle C2 centre (0, 0) radius 75
extrude "Extrude4" add sketch "Sketch4" along normal blind 5
sketch "Sketch1" plane through (0, 0, 28) normal (0, 0, 1) x axis (-1, 0, 0)
  circle C1 centre (0, 0) radius 75
sketch "Sketch5" plane through (0, 0, -65) normal (0, 0, -1) x axis (1, 0, 0)
  line L1 (-58.3333, -9.8601) -> (-28.3333, -9.8601)
  line L2 (-58.3333, 10.1399) -> (-58.3333, -9.8601)
  line L3 (-28.3333, 10.1399) -> (-58.3333, 10.1399)
  line L4 (-28.3333, -9.8601) -> (-28.3333, 10.1399)
  line L5 (58.3333, 9.8601) -> (28.3333, 9.8601)
  line L6 (58.3333, -10.1399) -> (58.3333, 9.8601)
  line L7 (28.3333, -10.1399) -> (58.3333, -10.1399)
  line L8 (28.3333, 9.8601) -> (28.3333, -10.1399)
  line L9 (10.1399, 28.3333) -> (-9.8601, 28.3333)
  line L10 (10.1399, 58.3333) -> (10.1399, 28.3333)
  line L11 (-9.8601, 58.3333) -> (10.1399, 58.3333)
  line L12 (-9.8601, 28.3333) -> (-9.8601, 58.3333)
  circle C1 centre (30, 0) radius 10
  circle C2 centre (-30, 0) radius 10
  circle C3 centre (0, 30) radius 10
  circle C4 centre (0, 0) radius 17
  circle C5 centre (0, 0) radius 30
  point P2 (30, 0)
  point P3 (-30, 0)
  point P5 (-28.3333, -9.8601)
  point P9 (28.3333, 9.8601)
  point P13 (-9.8601, 28.3333)
  point P6 (-58.3333, -9.8601)
  point P8 (-28.3333, 10.1399)
  point P10 (58.3333, 9.8601)
  point P12 (28.3333, -10.1399)
  point P14 (10.1399, 28.3333)
  point P16 (-9.8601, 58.3333)
  coincident P2 C5
  coincident P3 C5
  equal C1 C2
  equal C2 C3
  horizontal L1
  vertical L2
  horizontal L3
  vertical L4
  coincident C2 P5
  coincident P5 C5
  horizontal L5
  vertical L6
  horizontal L7
  vertical L8
  coincident C1 P9
  coincident P9 C5
  horizontal L9
  vertical L10
  horizontal L11
  vertical L12
  coincident C3 P13
  coincident P13 C5
  dimension "d53" diameter C2 = 20
  dimension "d128" distance P5 P6 = 30
  dimension "d129" distance P5 P8 = 20
  dimension "d130" distance P9 P10 = 30
  dimension "d131" distance P9 P12 = 20
  dimension "d138" distance P13 P14 = 20
  dimension "d139" distance P13 P16 = 30
extrude "Extrude7" add sketch "Sketch5" profile of C5 C1 C2 C3 against normal blind 5
split "Split1" bodies "Upper Half"
position "Position4"
hole "Hole1" HoleDepth 20 HoleDiameter 5 TipAngle 118
base_feature "Base Feature1"
position "Position5"
position "Position6"
sketch "Sketch5" plane through (0, 0, -28.015) normal (0, 0, -1) x axis (1, 0, 0)
  line L1 (11.25, 72.25) -> (11.25, 37.75)
  line L2 (-9.25, 74.25) -> (9.25, 74.25)
  line L3 (-11.25, 37.75) -> (-11.25, 72.25)
  line L4 (-7, 37.75) -> (-11.25, 37.75)
  line L5 (-7, 26.75) -> (-7, 37.75)
  line L6 (7, 26.75) -> (-7, 26.75)
  line L7 (7, 37.75) -> (7, 26.75)
  line L8 (11.25, 37.75) -> (7, 37.75)
  line L9 (-2.5, 30.2778) -> (-2.5, 29.2778)
  line L10 (-3.0407, 30.2778) -> (-2.5, 30.2778)
  line L11 (-3.0407, 33.2778) -> (-3.0407, 30.2778)
  line L12 (2.9593, 33.2778) -> (-3.0407, 33.2778)
  line L13 (2.9593, 30.2778) -> (2.9593, 33.2778)
  line L14 (2.5, 30.2778) -> (2.9593, 30.2778)
  line L15 (2.5, 29.2778) -> (2.5, 30.2778)
  line L16 (-2.5, 29.2778) -> (2.5, 29.2778)
  arc A1 centre (9.25, 72.25) radius 2 clockwise from (9.25, 74.25) to (11.25, 72.25)
  arc A2 centre (-9.25, 72.25) radius 2 clockwise from (-11.25, 72.25) to (-9.25, 74.25)
  circle C1 centre (9.25, 39.75) radius 1.25
  circle C2 centre (-8.75, 42.75) radius 1.5
  circle C3 centre (-9.25, 39.75) radius 1.25
  circle C4 centre (0, 63.25) radius 2.5
  circle C5 centre (8.75, 42.75) radius 1.5
sketch "Sketch6" plane through (0, 0, -28.015) normal (0, 0, -1) x axis (1, 0, 0)
component_insert "Component Insert2"
sketch "Sketch7" plane through (0, 0, -4.9) normal (0, 0, -1) x axis (1, 0, 0)
  circle C1 centre (0, 0) radius 32.9
  circle C2 centre (0, 0) radius 37
  circle C3 centre (0, 0) radius 37
  circle C4 centre (0, 0) radius 35.0718
  circle C5 centre (0, 0) radius 32.9
  point P1 (0, 0)
  point P3 (0, 0)
  coincident P1 P3
  concentric C3 C4
  dimension "d194" diameter C4 = 70.1436
extrude "Extrude8" add of existing geometry blind 10
offset_faces "OffsetFaces1" distance -13
position "Position7"
sketch "Sketch6" plane through (0, 0, 27.5216) normal (0, 0, 1) x axis (-1, 0, 0)
  circle C1 centre (-0.4415, -0.6384) radius 75
as_built_joint "As-built1"
as_built_joint "As-built2" OffsetX 0 OffsetY 0 OffsetZ 0 AngleZ 0
joint "Assemble1" alignAngle 0 alignOffsetX 0 alignOffsetY 0 alignOffsetZ 0
position "Position8"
